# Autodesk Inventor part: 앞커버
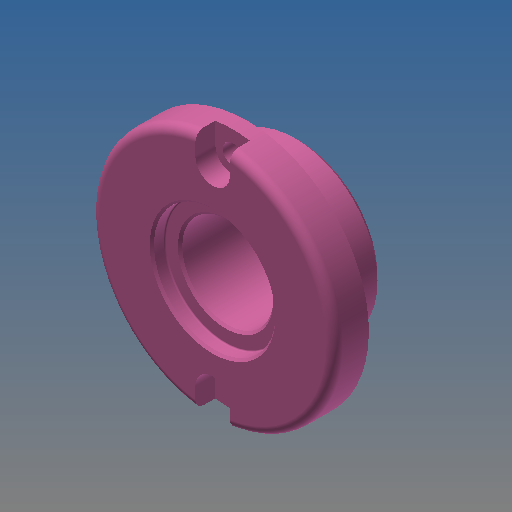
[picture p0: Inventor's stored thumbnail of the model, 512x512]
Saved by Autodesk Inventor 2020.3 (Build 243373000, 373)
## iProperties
Created: 2022-03
Part Number: 앞커버
Material: 일반
Document SubType Name: Modeling
Designer: mdu-01
Density: 1 g/cm^3
Appearance: 분홍색
Author: mdu-01
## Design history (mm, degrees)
sketch "스케치1"
  geometry: L1 (0, 0)-(0, -20); L2 (14, 0)-(28, 0); L3 (28, 0)-(28, -8); L4 (28, -8)-(19, -8); L5 (19, -8)-(19, -20); L6 (19, -20)-(10.5, -20); L7 (14, 0)-(14, -3); L8 (14, -3)-(10.5, -3); L9 (10.5, -3)-(10.5, -20)
  constraints: 18 end point, 5 perpendicular, 2 horizontal alignment, 2 parallel, 1 horizontal, 1 vertical
  dimensions: "d0" = 56 diameter of L3 L1; "d2" = 38 diameter of L5 L1; "d3" = 8 distance of L2.end L3.end; "d4" = 20 distance between parallel lines of L2 L6; "d5" = 21 diameter of L9 L1; "d6" = 28 diameter of L7 L1; "d7" = 3 distance of L2.start L7.end
revolve "회전1" sketch "스케치1" stored, may be unused: angle "d8" = 90 deg
fillet "모깎기1" dims "d9" = 0.5
chamfer "모따기1" distance "d10" = 0.5; stored, may be unused: second distance "d11" = 2, angle "d12" = 45 deg
chamfer "모따기2" distance "d13" = 1; stored, may be unused: second distance "d14" = 2, angle "d15" = 45 deg
fillet "모깎기2" dims "d32" = 2
sketch "스케치2" dims "d16" = 46
  geometry: 3 further points
  constraints: 2 vertical alignment, 1 coincident, 2 other
hole "구멍1" sketch "스케치2" at (0, 23) diameter "d18" = 4.5; stored, may be unused: countersink angle "d22" = 90 deg, drill point angle "d24" = 118 deg; dims "d19" = 6, "d20" = 8, "d21" = 4.6, "d23" = 8
sketch "스케치3"
  geometry: L1 (4, 23)-(4, 27.713); L2 (-4, 23)-(-4, 27.713); A1 r 4 centre (0, 23) between (-4, 23) and (4, 23) reference; A2 r 28 centre (0, 0) between (4, 27.713) and (-4, 27.713) reference; 1 further point
  constraints: 4 end point, 4 point on circle, 2 tangent, 1 parallel, 1 vertical
extrude "돌출1" cut sketch "스케치3" stored distance "d27" = 10; taper "d28" = 0 deg
fillet "모깎기3" dims "d33" = 0.3
node "솔리드1"
pattern_circular "원형 패턴1" dims angle "d30" = 360 deg
